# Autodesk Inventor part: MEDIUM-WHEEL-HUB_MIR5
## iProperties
Created: 2007-08
Part Number: MEDIUM-WHEEL-HUB_MIR5
Material: ABS Plastic
Document SubType Name: Modeling
Mass: 42.8255 g
Surface Area: 324.402 cm^2
Volume: 40.4014 cm^3
Density: 1.06 g/cm^3
